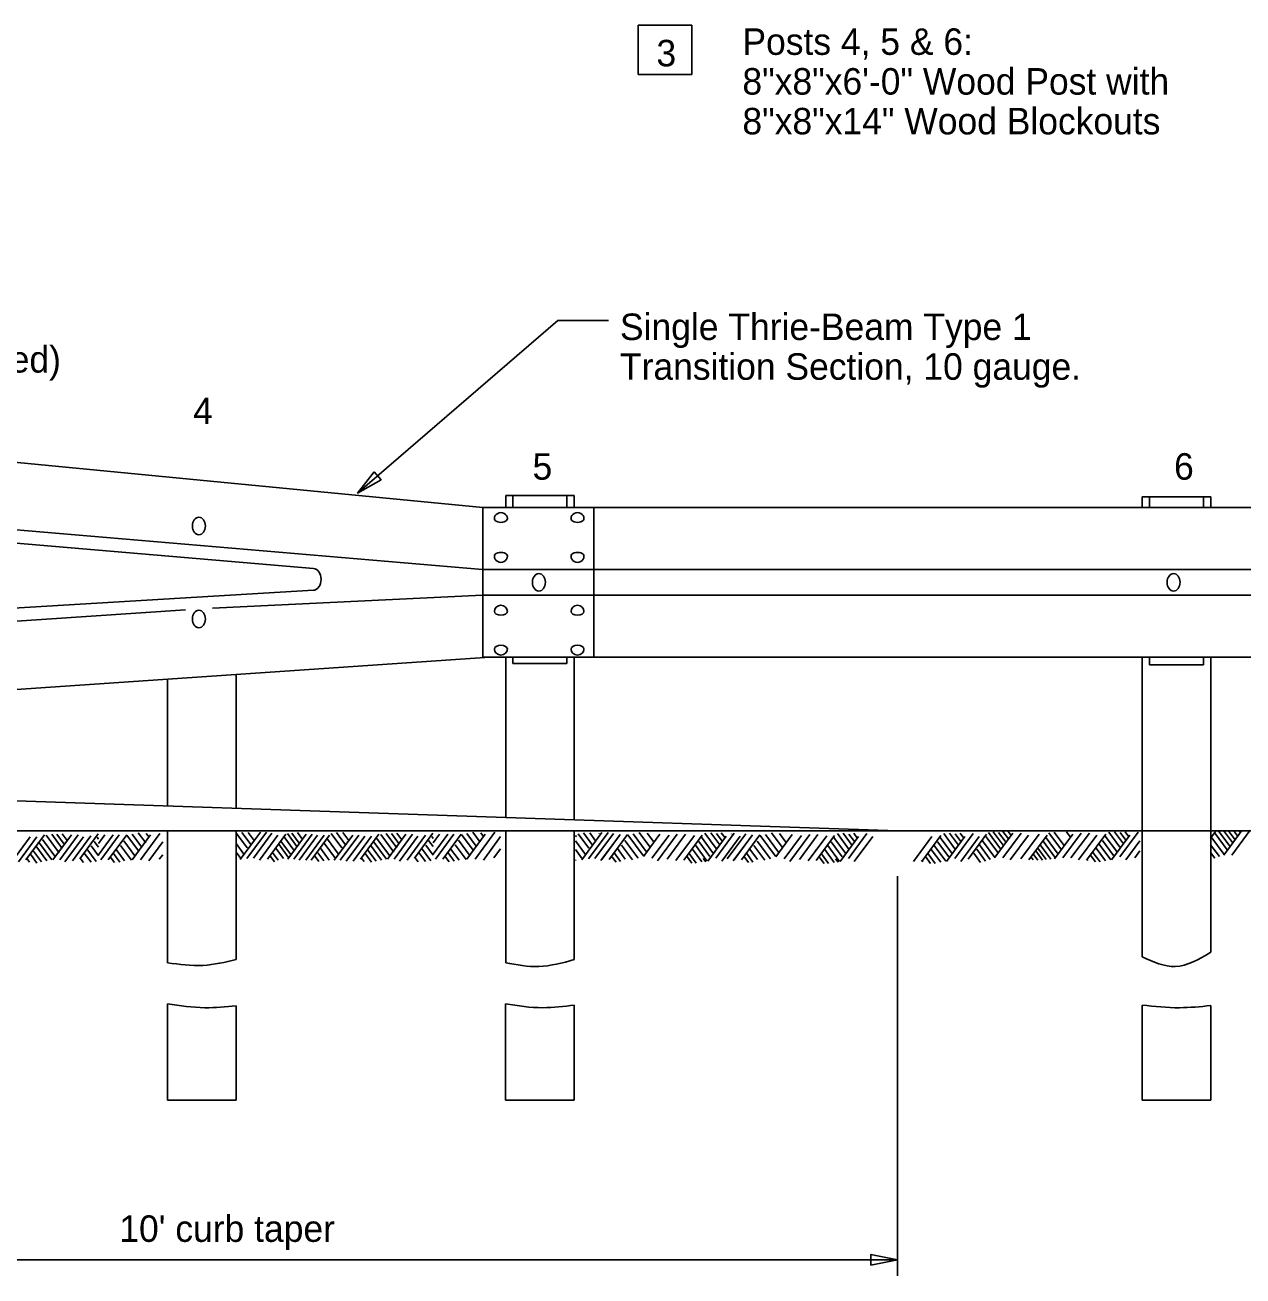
# Model space of a CAD drawing. Extents: x 0 to 34, y 0 to 22.
# Drawn here: x 12.13 to 18.56, y 8.02 to 14.63 of the extents above; entities that cross this region are included whole.
import ezdxf

# ---------------------------------------------------------------- set-up
doc = ezdxf.new("R2010")
doc.units = 0
doc.layers.add('ST_Details', color=7, linetype='Continuous')
doc.layers.add('ST_Text', color=7, linetype='Continuous')

msp = doc.modelspace()

# ---------------------------------------------------------------- linework, layer by layer
at = {"layer": 'ST_Details'}
for p, q in [((11.5347, 12.3733), (14.5458, 12.0817)), ((14.6667, 12.1461), (15.0291, 12.1461)), ((14.6667, 12.0829), (14.6667, 12.1461)), ((14.7046, 12.1461), (14.7046, 12.0817)), ((14.9904, 12.1461), (14.9904, 12.0837)), ((15.0291, 12.0837), (15.0291, 12.1461)), ((18.0277, 12.1392), (18.3908, 12.1392)), ((18.0277, 12.0817), (18.0277, 12.1392)), ((18.0665, 12.1392), (18.0665, 12.0817)), ((18.352, 12.1392), (18.352, 12.0817)), ((18.3908, 12.0817), (18.3908, 12.1392)), ((14.5458, 11.2925), (14.5458, 12.0817)), ((14.5458, 12.0817), (21.8542, 12.0817)), ((15.1314, 11.2925), (15.1314, 12.0817)), ((14.5441, 11.7547), (11.533, 12.0105)), ((13.0462, 11.9845), (13.0462, 11.9845)), ((13.6513, 11.7606), (11.5297, 11.94)), ((14.5441, 11.7547), (15.1987, 11.7547)), ((15.1987, 11.7547), (21.2687, 11.7547)), ((13.651, 11.6447), (11.5308, 11.5175)), ((14.8422, 11.687), (14.8422, 11.687)), ((18.1941, 11.687), (18.1941, 11.687)), ((14.5441, 11.6192), (13.1181, 11.5508)), ((14.5441, 11.6192), (15.1987, 11.6192)), ((15.1987, 11.6192), (21.2687, 11.6192)), ((12.9752, 11.5415), (11.533, 11.4447)), ((14.5825, 11.2925), (11.5347, 11.0842)), ((14.5441, 11.2925), (15.1987, 11.2925)), ((14.6667, 11.2928), (14.6667, 10.4449)), ((14.7046, 11.2925), (14.7046, 11.2581)), ((14.7046, 11.2581), (14.9904, 11.2581)), ((14.9904, 11.2925), (14.9904, 11.2581)), ((15.0291, 11.2925), (15.0291, 10.4326)), ((15.1987, 11.2925), (21.8542, 11.2925)), ((18.0283, 11.2916), (18.0283, 10.3748)), ((18.0665, 11.2925), (18.0665, 11.2511)), ((18.0665, 11.2511), (18.352, 11.2511)), ((18.352, 11.2932), (18.352, 11.2511)), ((18.3908, 11.2932), (18.3908, 10.3748)), ((12.8811, 11.1768), (12.8811, 10.5053)), ((13.2436, 11.202), (13.2436, 10.4931)), ((11.0284, 10.5681), (16.7358, 10.3748)), ((13.2436, 10.3748), (11.6743, 10.3748)), ((12.8811, 10.3748), (12.8811, 9.6772)), ((13.2436, 10.3748), (13.2436, 9.694)), ((15.0291, 10.3748), (13.2436, 10.3748)), ((14.6103, 10.3748), (13.4778, 10.3748)), ((14.6667, 10.3748), (14.6667, 9.6772)), ((15.0291, 10.3748), (15.0291, 9.694)), ((16.2472, 10.3748), (15.0291, 10.3748)), ((18.3908, 10.3748), (16.2472, 10.3748)), ((18.0283, 10.3748), (18.0283, 9.7082)), ((18.3908, 10.3748), (18.3908, 9.733)), ((21.752, 10.3748), (18.3908, 10.3748)), ((18.4912, 10.2939), (18.4297, 10.377)), ((18.5052, 10.3131), (18.4579, 10.377)), ((18.459, 10.2463), (18.5554, 10.377)), ((18.5201, 10.3273), (18.4833, 10.377)), ((18.5023, 10.2463), (18.5994, 10.3778)), ((18.5322, 10.3475), (18.5102, 10.377)), ((18.5476, 10.3647), (18.5384, 10.377)), ((12.0578, 10.211), (12.1548, 10.3424)), ((12.0935, 10.211), (12.1906, 10.3424)), ((12.133, 10.2217), (12.2301, 10.3532)), ((12.2697, 10.2213), (12.1998, 10.3161)), ((12.2855, 10.2403), (12.2196, 10.3295)), ((12.308, 10.258), (12.2393, 10.3509)), ((12.325, 10.2807), (12.269, 10.3563)), ((12.2757, 10.2217), (12.3727, 10.3532)), ((12.3355, 10.3038), (12.2968, 10.3563)), ((12.3113, 10.2217), (12.4082, 10.3532)), ((12.3504, 10.3239), (12.3246, 10.3589)), ((12.3389, 10.211), (12.4361, 10.3424)), ((12.3786, 10.2165), (12.4757, 10.348)), ((12.4182, 10.2272), (12.5151, 10.3587)), ((12.5161, 10.2875), (12.4928, 10.3187)), ((12.5161, 10.3303), (12.5086, 10.3402)), ((12.5161, 10.3071), (12.5501, 10.3532)), ((12.5161, 10.248), (12.5936, 10.3532)), ((12.5282, 10.2217), (12.6254, 10.3532)), ((12.5679, 10.2217), (12.6651, 10.3532)), ((12.7087, 10.2426), (12.6503, 10.3215)), ((12.7277, 10.268), (12.6663, 10.3509)), ((12.7435, 10.2895), (12.6939, 10.3563)), ((12.6946, 10.2217), (12.7916, 10.3532)), ((12.7653, 10.3115), (12.7264, 10.3639)), ((12.7382, 10.2217), (12.8397, 10.3595)), ((12.7829, 10.3409), (12.7687, 10.3601)), ((12.7818, 10.2165), (12.8552, 10.3159)), ((13.2842, 10.2513), (13.2424, 10.3082)), ((13.3009, 10.2848), (13.2454, 10.3601)), ((13.265, 10.2232), (13.3709, 10.3667)), ((13.3217, 10.2997), (13.2733, 10.3655)), ((13.3002, 10.228), (13.4029, 10.3671)), ((13.3377, 10.3237), (13.3067, 10.3655)), ((13.334, 10.2309), (13.431, 10.3623)), ((13.3658, 10.2202), (13.4628, 10.3516)), ((13.4092, 10.2256), (13.5064, 10.3571)), ((13.5308, 10.2508), (13.4799, 10.3198)), ((13.5485, 10.2726), (13.4957, 10.3438)), ((13.564, 10.2916), (13.5136, 10.3601)), ((13.5162, 10.2256), (13.6132, 10.3571)), ((13.5762, 10.3101), (13.5375, 10.3627)), ((13.5478, 10.2256), (13.6448, 10.3571)), ((13.5906, 10.3337), (13.5672, 10.3655)), ((13.5755, 10.2202), (13.6726, 10.3516)), ((13.6113, 10.2202), (13.7082, 10.3516)), ((13.6389, 10.2202), (13.7362, 10.3516)), ((13.7681, 10.2275), (13.7078, 10.3091)), ((13.784, 10.2513), (13.7255, 10.3307)), ((13.8009, 10.2848), (13.7452, 10.3601)), ((13.7617, 10.2202), (13.8587, 10.3516)), ((13.8214, 10.2997), (13.773, 10.3655)), ((13.7934, 10.2202), (13.8905, 10.3516)), ((13.8375, 10.3237), (13.8066, 10.3655)), ((13.8251, 10.2149), (13.9222, 10.3464)), ((13.8607, 10.2149), (13.9577, 10.3464)), ((13.9002, 10.2256), (13.9972, 10.3571)), ((14.037, 10.225), (13.9671, 10.3198)), ((14.0527, 10.244), (13.9867, 10.3332)), ((14.0753, 10.2617), (14.0067, 10.3547)), ((14.0921, 10.2845), (14.0363, 10.3601)), ((14.0428, 10.2256), (14.1399, 10.3571)), ((14.1027, 10.3076), (14.064, 10.3601)), ((14.0784, 10.2256), (14.1754, 10.3571)), ((14.1176, 10.3277), (14.0917, 10.3627)), ((14.1062, 10.2149), (14.2032, 10.3464)), ((14.1458, 10.2202), (14.2429, 10.3516)), ((14.1855, 10.2309), (14.2825, 10.3623)), ((14.2832, 10.2912), (14.2599, 10.3226)), ((14.2832, 10.3341), (14.2758, 10.3438)), ((14.2832, 10.3107), (14.3174, 10.3571)), ((14.2832, 10.2519), (14.3609, 10.3571)), ((14.2955, 10.2256), (14.3926, 10.3571)), ((14.3352, 10.2256), (14.4323, 10.3571)), ((14.4759, 10.2463), (14.4176, 10.3253)), ((14.4947, 10.2717), (14.4334, 10.3547)), ((14.5107, 10.2932), (14.4612, 10.3601)), ((14.4617, 10.2256), (14.559, 10.3571)), ((14.5325, 10.3152), (14.4936, 10.3677)), ((14.5054, 10.2256), (14.6094, 10.3667)), ((14.5501, 10.3448), (14.5359, 10.3639)), ((14.5487, 10.2202), (14.6402, 10.3437)), ((15.0352, 10.3431), (15.0404, 10.3497)), ((15.0886, 10.2493), (15.0352, 10.3213)), ((15.1052, 10.2829), (15.0496, 10.3582)), ((15.0692, 10.2213), (15.1752, 10.3649)), ((15.1258, 10.2979), (15.0775, 10.3637)), ((15.1044, 10.2262), (15.2072, 10.3652)), ((15.1419, 10.3217), (15.111, 10.3637)), ((15.1382, 10.2291), (15.2353, 10.3605)), ((15.16, 10.3594), (15.1607, 10.3605)), ((15.1699, 10.2185), (15.2671, 10.3497)), ((15.174, 10.2237), (15.2709, 10.3552)), ((15.2134, 10.2237), (15.3106, 10.3552)), ((15.3657, 10.2292), (15.296, 10.3233)), ((15.3926, 10.2438), (15.3119, 10.3529)), ((15.4087, 10.2646), (15.3396, 10.3582)), ((15.428, 10.2902), (15.372, 10.3659)), ((15.3939, 10.2392), (15.4811, 10.3571)), ((15.4472, 10.3173), (15.4144, 10.3621)), ((15.4393, 10.2293), (15.5298, 10.3516)), ((15.4687, 10.2152), (15.5732, 10.3571)), ((15.5199, 10.2256), (15.617, 10.3571)), ((15.5658, 10.2185), (15.6631, 10.3497)), ((15.6071, 10.2202), (15.7041, 10.3516)), ((15.7455, 10.2387), (15.6869, 10.3182)), ((15.7616, 10.2587), (15.7008, 10.341)), ((15.7787, 10.2818), (15.7193, 10.3621)), ((15.7337, 10.2149), (15.8308, 10.3464)), ((15.7976, 10.2999), (15.7504, 10.3639)), ((15.7774, 10.2309), (15.8743, 10.3623)), ((15.8096, 10.3198), (15.78, 10.3601)), ((15.8252, 10.3372), (15.8055, 10.3639)), ((15.809, 10.2149), (15.9059, 10.3464)), ((15.8373, 10.2265), (15.9344, 10.3579)), ((15.8591, 10.3568), (15.8598, 10.3579)), ((15.869, 10.2159), (15.9662, 10.3472)), ((15.8731, 10.2212), (15.97, 10.3527)), ((15.9125, 10.2212), (16.0097, 10.3527)), ((16.0648, 10.2267), (15.9951, 10.3207)), ((16.0917, 10.2412), (16.011, 10.3503)), ((16.1078, 10.262), (16.0387, 10.3556)), ((16.1271, 10.2876), (16.0711, 10.3633)), ((16.093, 10.2366), (16.1802, 10.3545)), ((16.1462, 10.3147), (16.1135, 10.3595)), ((16.1384, 10.2267), (16.2289, 10.349)), ((16.1677, 10.2127), (16.2723, 10.3545)), ((16.219, 10.223), (16.3161, 10.3545)), ((16.2649, 10.2159), (16.3622, 10.3472)), ((16.3062, 10.2177), (16.4032, 10.349)), ((16.4446, 10.2362), (16.386, 10.3156)), ((16.4607, 10.2562), (16.3999, 10.3384)), ((16.4777, 10.2792), (16.4184, 10.3595)), ((16.4328, 10.2123), (16.5299, 10.3438)), ((16.4967, 10.2973), (16.4495, 10.3613)), ((16.4765, 10.2283), (16.5734, 10.3597)), ((16.5087, 10.3172), (16.4791, 10.3575)), ((16.5243, 10.3347), (16.5046, 10.3613)), ((16.5081, 10.2123), (16.605, 10.3438)), ((16.8207, 10.213), (16.9177, 10.3445)), ((16.8681, 10.2185), (16.9652, 10.3497)), ((17.0065, 10.2367), (16.948, 10.3161)), ((17.0229, 10.2568), (16.9621, 10.3392)), ((17.0397, 10.2797), (16.9806, 10.3602)), ((16.9949, 10.213), (17.092, 10.3445)), ((17.0589, 10.2981), (17.0114, 10.3621)), ((17.0384, 10.2291), (17.1357, 10.3605)), ((17.0708, 10.3182), (17.0411, 10.3582)), ((17.0864, 10.3353), (17.0665, 10.3621)), ((17.0701, 10.213), (17.1672, 10.3445)), ((17.1094, 10.2256), (17.2067, 10.3573)), ((17.2502, 10.2339), (17.1852, 10.3217)), ((17.2672, 10.2586), (17.2035, 10.3447)), ((17.2806, 10.2787), (17.2162, 10.3657)), ((17.2946, 10.2979), (17.2417, 10.3695)), ((17.2482, 10.2312), (17.3453, 10.3627)), ((17.3093, 10.3122), (17.2699, 10.3657)), ((17.2918, 10.2312), (17.3889, 10.3627)), ((17.3215, 10.3324), (17.2926, 10.3715)), ((17.337, 10.3496), (17.3208, 10.3715)), ((17.3313, 10.2204), (17.4286, 10.3519)), ((17.3868, 10.2259), (17.484, 10.3573)), ((17.4304, 10.2204), (17.5274, 10.3519)), ((17.5677, 10.2357), (17.5057, 10.3197)), ((17.5839, 10.252), (17.5212, 10.3371)), ((17.6017, 10.2739), (17.5353, 10.3638)), ((17.6142, 10.2987), (17.5636, 10.3677)), ((17.5649, 10.2259), (17.6621, 10.3573)), ((17.6087, 10.2312), (17.7058, 10.3627)), ((17.6482, 10.3427), (17.6285, 10.3695)), ((17.6521, 10.2312), (17.7493, 10.3627)), ((17.6917, 10.2204), (17.7888, 10.3519)), ((17.7392, 10.2259), (17.8363, 10.3573)), ((17.8777, 10.2443), (17.8192, 10.3237)), ((17.8939, 10.2645), (17.8332, 10.3467)), ((17.9108, 10.2873), (17.8516, 10.3677)), ((17.8659, 10.2204), (17.9631, 10.3519)), ((17.9298, 10.3055), (17.8826, 10.3695)), ((17.9095, 10.2366), (18.0066, 10.368)), ((17.9418, 10.3255), (17.9122, 10.3657)), ((17.9575, 10.3427), (17.9377, 10.3695)), ((17.9412, 10.2204), (18.0164, 10.3223)), ((18.3897, 10.3349), (18.4174, 10.3724)), ((18.4609, 10.249), (18.3958, 10.3369)), ((18.4777, 10.2737), (18.4142, 10.3597)), ((12.1912, 10.2043), (12.1582, 10.249)), ((12.2148, 10.21), (12.172, 10.2677)), ((12.2437, 10.2165), (12.186, 10.2946)), ((12.4767, 10.2092), (12.4412, 10.257)), ((12.5044, 10.2119), (12.4551, 10.2785)), ((12.5161, 10.2417), (12.4769, 10.2946)), ((12.6281, 10.2097), (12.5949, 10.2545)), ((12.6534, 10.2156), (12.609, 10.2759)), ((12.6902, 10.2193), (12.6327, 10.2973)), ((12.8374, 10.224), (12.8552, 10.248)), ((13.2682, 10.2275), (13.2424, 10.2626)), ((13.3042, 10.2804), (13.3033, 10.2817)), ((13.4452, 10.2114), (13.4206, 10.2447)), ((13.4646, 10.2201), (13.4345, 10.2608)), ((13.4926, 10.2277), (13.4522, 10.2822)), ((13.5182, 10.2359), (13.4681, 10.3038)), ((13.6794, 10.2133), (13.655, 10.2465)), ((13.7057, 10.2151), (13.6739, 10.2582)), ((13.7337, 10.2202), (13.6878, 10.2822)), ((13.8041, 10.2804), (13.8032, 10.2817)), ((13.9583, 10.2082), (13.9255, 10.2529)), ((13.9819, 10.2138), (13.9392, 10.2716)), ((14.0109, 10.2202), (13.9531, 10.2985)), ((14.2438, 10.213), (14.2085, 10.2608)), ((14.2716, 10.2157), (14.2225, 10.2822)), ((14.2832, 10.2456), (14.2442, 10.2985)), ((14.3952, 10.2137), (14.3622, 10.2582)), ((14.4207, 10.2193), (14.376, 10.2797)), ((14.4575, 10.2232), (14.3998, 10.3012)), ((14.6046, 10.2316), (14.6402, 10.2797)), ((15.0723, 10.2256), (15.0352, 10.2757)), ((15.1085, 10.2787), (15.1076, 10.2797)), ((15.2494, 10.2096), (15.2247, 10.2429)), ((15.2736, 10.2117), (15.2406, 10.2565)), ((15.2969, 10.2256), (15.2566, 10.2804)), ((15.3357, 10.2213), (15.2782, 10.2993)), ((15.6083, 10.2787), (15.6074, 10.2797)), ((15.6495, 10.2043), (15.6218, 10.2416)), ((15.6734, 10.2043), (15.636, 10.255)), ((15.7031, 10.21), (15.6529, 10.2779)), ((15.7299, 10.2157), (15.6685, 10.2989)), ((15.9727, 10.2092), (15.9397, 10.2539)), ((15.996, 10.223), (15.9557, 10.2778)), ((16.0347, 10.2187), (15.9773, 10.2967)), ((16.3074, 10.2761), (16.3065, 10.2772)), ((16.3725, 10.2017), (16.3351, 10.2524)), ((16.4022, 10.2074), (16.352, 10.2753)), ((16.429, 10.2132), (16.3676, 10.2963)), ((16.9347, 10.2024), (16.8972, 10.2531)), ((16.9643, 10.2082), (16.9142, 10.276)), ((16.9912, 10.2138), (16.9297, 10.2971)), ((17.1747, 10.208), (17.1395, 10.2557)), ((17.2007, 10.2147), (17.1549, 10.2767)), ((17.2256, 10.2233), (17.1683, 10.3008)), ((17.4776, 10.2186), (17.4548, 10.2492)), ((17.5021, 10.2194), (17.4661, 10.2682)), ((17.5221, 10.2233), (17.4776, 10.2836)), ((17.5466, 10.2243), (17.4902, 10.3008)), ((17.7817, 10.2098), (17.7541, 10.2472)), ((17.8057, 10.2098), (17.7682, 10.2607)), ((17.8354, 10.2157), (17.7852, 10.2836)), ((17.8622, 10.2215), (17.8007, 10.3045)), ((17.9887, 10.2312), (18.0164, 10.2687)), ((18.4361, 10.2384), (18.3897, 10.3013)), ((18.4114, 10.2298), (18.3897, 10.2594)), ((12.1519, 10.2096), (12.1388, 10.2272)), ((12.4368, 10.2068), (12.4196, 10.2302)), ((12.6006, 10.2068), (12.5782, 10.2369)), ((13.9189, 10.2133), (13.906, 10.2309)), ((14.2041, 10.2107), (14.1868, 10.2339)), ((14.3677, 10.2107), (14.3455, 10.2407)), ((15.0381, 10.2183), (15.0352, 10.222)), ((15.7232, 10.2114), (15.7102, 10.2291)), ((15.9485, 10.207), (15.9238, 10.2403)), ((16.3486, 10.2017), (16.3209, 10.239)), ((16.4222, 10.2088), (16.4092, 10.2265)), ((16.8698, 10.2098), (16.8634, 10.2186)), ((16.9107, 10.2024), (16.8831, 10.2397)), ((17.4528, 10.2215), (17.4421, 10.2357)), ((17.7408, 10.2174), (17.7343, 10.2262)), ((12.8809, 9.4602), (12.8809, 9.4539)), ((12.8809, 9.4538), (12.8809, 8.9514)), ((13.2437, 9.4507), (13.2437, 8.9514)), ((14.6665, 9.4602), (14.6665, 9.4539)), ((14.6665, 9.4538), (14.6665, 8.9514)), ((15.0291, 9.4544), (15.0291, 8.9514)), ((18.0282, 9.4538), (18.0282, 8.9514)), ((18.391, 9.4514), (18.391, 8.9514)), ((12.8809, 8.9514), (13.2437, 8.9514)), ((14.6665, 8.9514), (15.0291, 8.9514)), ((18.0282, 8.9514), (18.391, 8.9514))]:
    msp.add_line(p, q, dxfattribs=at)
for centre in [(13.0464, 11.9846), (14.8424, 11.6871), (18.1943, 11.6871), (13.0464, 11.4932)]:
    msp.add_ellipse(centre, major_axis=(0, 0.0463), ratio=0.738563, dxfattribs=at)
for centre, major_axis, ratio, start_param, end_param in [((14.6415, 12.0238), (0.0342, 0), 0.920676, 0, 3.141593), ((15.0461, 12.0238), (0.0342, 0), 0.920676, 0, 3.141593), ((14.6415, 12.0238), (-0.0342, 0), 0.587975, 0, 3.141593), ((15.0461, 12.0238), (-0.0342, 0), 0.587975, 0, 3.141593), ((14.6415, 11.8247), (0.0342, 0), 0.599655, 0, 3.141593), ((15.0461, 11.8247), (0.0342, 0), 0.599655, 0, 3.141593), ((14.6415, 11.8247), (-0.0342, 0), 0.943283, 0, 3.141593), ((15.0461, 11.8247), (-0.0342, 0), 0.943283, 0, 3.141593), ((13.649, 11.7026), (0, -0.058), 0.738563, 0.049283, 3.084561), ((14.6415, 11.5335), (-0.0342, 0), 0.943283, 3.141593, 6.283185), ((15.0461, 11.5335), (-0.0342, 0), 0.943283, 3.141593, 6.283185), ((14.6415, 11.5335), (0.0342, 0), 0.599655, 3.141593, 6.283185), ((15.0461, 11.5335), (0.0342, 0), 0.599655, 3.141593, 6.283185), ((14.6415, 11.3344), (-0.0342, 0), 0.587975, 3.141593, 6.283185), ((14.6415, 11.3344), (0.0342, 0), 0.920676, 3.141593, 6.283185), ((15.0461, 11.3344), (-0.0342, 0), 0.587975, 3.141593, 6.283185), ((15.0461, 11.3344), (0.0342, 0), 0.920676, 3.141593, 6.283185)]:
    msp.add_ellipse(centre, major_axis=major_axis, ratio=ratio, start_param=start_param, end_param=end_param, dxfattribs=at)
for points in [[(18.3908, 9.733), (18.2031, 9.658), (18.0283, 9.7082)], [(13.2436, 9.694), (13.0674, 9.664), (12.8806, 9.6772)], [(15.0291, 9.694), (14.8413, 9.658), (14.6667, 9.6772)], [(13.2437, 9.4507), (13.0779, 9.4401), (12.8809, 9.4602)], [(15.0291, 9.4544), (14.8636, 9.4401), (14.6665, 9.4602)], [(18.391, 9.4514), (18.2252, 9.4401), (18.0282, 9.4539)]]:
    msp.add_spline(points, degree=3, dxfattribs=at)
at = {"layer": 'ST_Text'}
for p, q in [((15.3661, 14.6305), (15.3661, 14.3687)), ((15.65, 14.6305), (15.3661, 14.6305)), ((15.65, 14.3687), (15.65, 14.6305)), ((15.3661, 14.3687), (15.65, 14.3687)), ((14.9422, 13.0702), (13.8844, 12.1582)), ((14.9422, 13.0702), (15.2098, 13.0702)), ((16.7358, 9.6197), (16.7358, 10.135)), ((16.7358, 9.6197), (16.7358, 8.0232)), ((5.3042, 8.1088), (16.7358, 8.1088))]:
    msp.add_line(p, q, dxfattribs=at)
for points in [[(13.9722, 12.2709), (14.0087, 12.2285), (13.8844, 12.1582)], [(16.5958, 8.0808), (16.5958, 8.1368), (16.7358, 8.1088)]]:
    msp.add_lwpolyline(points, close=True, dxfattribs=at)

# ---------------------------------------------------------------- texts
for s, p in [('Posts 4, 5 & 6:', (15.917, 14.4729)), ('3', (15.4629, 14.4121)), ('8"x8"x6\'-0" Wood Post with', (15.917, 14.2629)), ('8"x8"x14" Wood Blockouts', (15.917, 14.0529)), ('Single Thrie-Beam Type 1', (15.2703, 12.9667)), ('Two Thrie-Beam Rail Sections (nested)', (9.0509, 12.7948)), ('Transition Section, 10 gauge.', (15.2703, 12.7567)), ('4', (13.0159, 12.5227)), ('5', (14.8085, 12.229)), ('6', (18.1967, 12.229)), ("10' curb taper", (12.626, 8.2034))]:
    msp.add_text(s, height=0.14, dxfattribs=at).set_placement(p)

doc.saveas('drawing.dxf')
